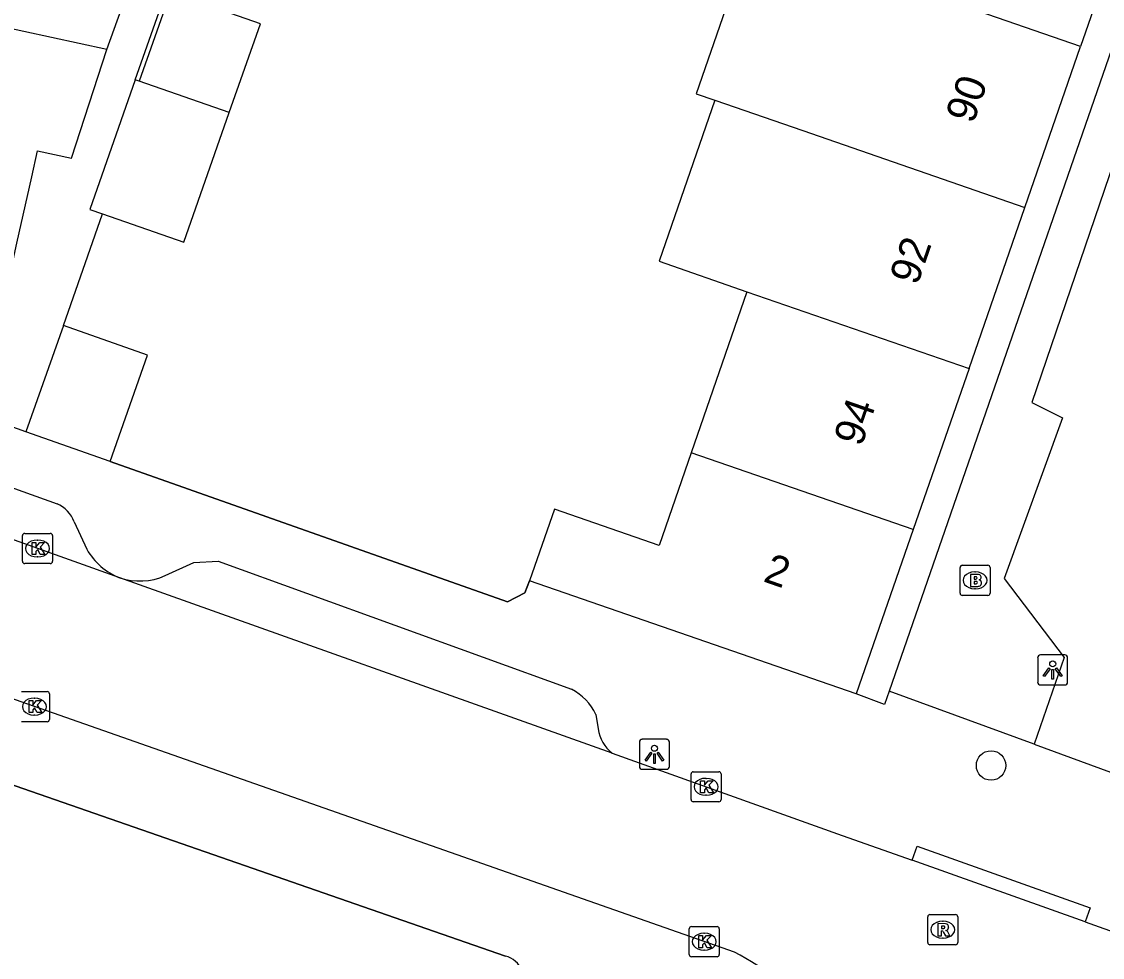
# Model space of a CAD drawing. Extents: x 160356 to 161355, y 381727 to 382845.
# Drawn here: x 160605.96 to 160641.88, y 382098.93 to 382130.04 of the extents above; entities that cross this region are included whole.
import ezdxf

# ---------------------------------------------------------------- set-up
doc = ezdxf.new("R2010")
doc.units = 0
for name, color, linetype in [('IMGEO_Boom', 7, 'Continuous'), ('IMGEO_Brandkraan', 7, 'Continuous'), ('IMGEO_Kolk', 7, 'Continuous'), ('IMGEO_Lichtpunt', 7, 'Continuous'), ('IMGEO_Muur', 7, 'Continuous'), ('IMGEO_Pand', 7, 'Continuous'), ('IMGEO_Pand_nummerreeks', 7, 'Continuous'), ('IMGEO_Rijbaan_lokaal_open', 7, 'Continuous'), ('IMGEO_Rioolput', 7, 'Continuous'), ('IMGEO_Voetpad_open', 7, 'Continuous')]:
    doc.layers.add(name, color=color, linetype=linetype)

msp = doc.modelspace()

# ---------------------------------------------------------------- linework, layer by layer
at = {"layer": 'IMGEO_Boom'}
msp.add_circle((160638.18, 382105.312), 0.489, dxfattribs=at)
at = {"layer": 'IMGEO_Brandkraan'}
for p, q in [((160637.148, 382111.039), (160637.148, 382111.891)), ((160637.223, 382111.965), (160638.075, 382111.965)), ((160637.636, 382111.745), (160637.661, 382111.745)), ((160638.149, 382111.891), (160638.149, 382111.039)), ((160637.659, 382111.185), (160637.634, 382111.185)), ((160638.075, 382110.965), (160637.223, 382110.965))]:
    msp.add_line(p, q, dxfattribs=at)
for points in [[(160637.148, 382111.039), (160637.148, 382111.891)], [(160637.223, 382111.965), (160638.075, 382111.965)], [(160638.149, 382111.891), (160638.149, 382111.039)], [(160637.496, 382111.665), (160637.496, 382111.265), (160637.709, 382111.265)], [(160637.727, 382111.665), (160637.496, 382111.665)], [(160637.675, 382111.584), (160637.621, 382111.584), (160637.621, 382111.508)], [(160637.621, 382111.508), (160637.674, 382111.508)], [(160637.683, 382111.432), (160637.621, 382111.432), (160637.621, 382111.351)], [(160637.621, 382111.351), (160637.683, 382111.351)], [(160638.075, 382110.965), (160637.223, 382110.965)]]:
    msp.add_lwpolyline(points, dxfattribs=at)
for centre, radius, start, end in [((160637.225, 382111.889), 0.0765, 91.552, 178.448), ((160637.225, 382111.889), 0.0765, 91.552, 178.448), ((160638.073, 382111.889), 0.0765, 1.552, 88.448), ((160638.073, 382111.889), 0.0765, 1.552, 88.448), ((160637.676, 382111.546), 0.0379, 267.8285, 90.9355), ((160637.684, 382111.391), 0.0404, 269.8759, 90.5077), ((160637.731, 382111.52), 0.145, 59.4692, 91.5367), ((160637.756, 382111.567), 0.0922, 285.5137, 58.1501), ((160637.761, 382111.375), 0.105, 301.3115, 78.989), ((160637.225, 382111.041), 0.0765, 181.552, 268.448), ((160637.225, 382111.041), 0.0765, 181.552, 268.448), ((160637.715, 382111.516), 0.251, 268.6676, 293.5347), ((160638.073, 382111.041), 0.0765, 271.552, 358.448), ((160638.073, 382111.041), 0.0765, 271.552, 358.448)]:
    msp.add_arc(centre, radius, start, end, dxfattribs=at)
for centre, major_axis, ratio, start_param, end_param in [((160637.635, 382111.465), (-0.387, 0.002), 0.722429, 4.712389, 7.853982), ((160637.66, 382111.465), (-0.39, 0.002), 0.717154, 1.570796, 4.712389)]:
    msp.add_ellipse(centre, major_axis=major_axis, ratio=ratio, start_param=start_param, end_param=end_param, dxfattribs=at)
at = {"layer": 'IMGEO_Kolk'}
for p, q in [((160605.992, 382112.099), (160605.992, 382112.951)), ((160606.067, 382113.025), (160606.919, 382113.025)), ((160606.48, 382112.805), (160606.505, 382112.805)), ((160606.993, 382112.951), (160606.993, 382112.099)), ((160606.503, 382112.245), (160606.478, 382112.245)), ((160606.919, 382112.025), (160606.067, 382112.025)), ((160605.965, 382107.769), (160606.817, 382107.769)), ((160606.378, 382107.549), (160606.403, 382107.549)), ((160606.891, 382107.695), (160606.891, 382106.843)), ((160606.817, 382106.769), (160605.965, 382106.769)), ((160606.401, 382106.989), (160606.376, 382106.989)), ((160628.209, 382104.179), (160628.209, 382105.031)), ((160628.284, 382105.105), (160629.136, 382105.105)), ((160628.697, 382104.885), (160628.722, 382104.885)), ((160629.21, 382105.031), (160629.21, 382104.179)), ((160628.72, 382104.325), (160628.695, 382104.325)), ((160629.136, 382104.105), (160628.284, 382104.105)), ((160628.148, 382099.031), (160628.148, 382099.883)), ((160628.223, 382099.957), (160629.075, 382099.957)), ((160629.149, 382099.883), (160629.149, 382099.031)), ((160628.636, 382099.737), (160628.661, 382099.737)), ((160628.659, 382099.177), (160628.634, 382099.177)), ((160629.075, 382098.957), (160628.223, 382098.957))]:
    msp.add_line(p, q, dxfattribs=at)
for points in [[(160605.992, 382112.099), (160605.992, 382112.951)], [(160606.067, 382113.025), (160606.919, 382113.025)], [(160606.993, 382112.951), (160606.993, 382112.099)], [(160606.313, 382112.725), (160606.436, 382112.725), (160606.436, 382112.574), (160606.566, 382112.725), (160606.73, 382112.725), (160606.584, 382112.574), (160606.737, 382112.325), (160606.585, 382112.325), (160606.5, 382112.489), (160606.436, 382112.422), (160606.436, 382112.325), (160606.313, 382112.325), (160606.313, 382112.725)], [(160606.919, 382112.025), (160606.067, 382112.025)], [(160605.965, 382107.769), (160606.817, 382107.769)], [(160606.211, 382107.469), (160606.334, 382107.469), (160606.334, 382107.318), (160606.464, 382107.469), (160606.628, 382107.469), (160606.482, 382107.318), (160606.635, 382107.069), (160606.483, 382107.069), (160606.398, 382107.233), (160606.334, 382107.166), (160606.334, 382107.069), (160606.211, 382107.069), (160606.211, 382107.469)], [(160606.891, 382107.695), (160606.891, 382106.843)], [(160606.817, 382106.769), (160605.965, 382106.769)], [(160628.209, 382104.179), (160628.209, 382105.031)], [(160628.284, 382105.105), (160629.136, 382105.105)], [(160629.21, 382105.031), (160629.21, 382104.179)], [(160628.53, 382104.805), (160628.653, 382104.805), (160628.653, 382104.654), (160628.783, 382104.805), (160628.947, 382104.805), (160628.801, 382104.654), (160628.954, 382104.405), (160628.802, 382104.405), (160628.717, 382104.569), (160628.653, 382104.502), (160628.653, 382104.405), (160628.53, 382104.405), (160628.53, 382104.805)], [(160629.136, 382104.105), (160628.284, 382104.105)], [(160628.148, 382099.031), (160628.148, 382099.883)], [(160628.223, 382099.957), (160629.075, 382099.957)], [(160629.149, 382099.883), (160629.149, 382099.031)], [(160628.469, 382099.657), (160628.592, 382099.657), (160628.592, 382099.506), (160628.722, 382099.657), (160628.886, 382099.657), (160628.74, 382099.506), (160628.893, 382099.257), (160628.741, 382099.257), (160628.656, 382099.421), (160628.592, 382099.354), (160628.592, 382099.257), (160628.469, 382099.257), (160628.469, 382099.657)], [(160629.075, 382098.957), (160628.223, 382098.957)]]:
    msp.add_lwpolyline(points, dxfattribs=at)
for centre, start, end in [((160606.069, 382112.949), 91.552, 178.448), ((160606.069, 382112.949), 91.552, 178.448), ((160606.917, 382112.949), 1.552, 88.448), ((160606.917, 382112.949), 1.552, 88.448), ((160606.069, 382112.101), 181.552, 268.448), ((160606.069, 382112.101), 181.552, 268.448), ((160606.917, 382112.101), 271.552, 358.448), ((160606.917, 382112.101), 271.552, 358.448), ((160606.815, 382107.693), 1.552, 88.448), ((160606.815, 382107.693), 1.552, 88.448), ((160606.815, 382106.845), 271.552, 358.448), ((160606.815, 382106.845), 271.552, 358.448), ((160628.286, 382105.029), 91.552, 178.448), ((160628.286, 382105.029), 91.552, 178.448), ((160629.134, 382105.029), 1.552, 88.448), ((160629.134, 382105.029), 1.552, 88.448), ((160628.286, 382104.181), 181.552, 268.448), ((160628.286, 382104.181), 181.552, 268.448), ((160629.134, 382104.181), 271.552, 358.448), ((160629.134, 382104.181), 271.552, 358.448), ((160628.225, 382099.881), 91.552, 178.448), ((160628.225, 382099.881), 91.552, 178.448), ((160629.073, 382099.881), 1.552, 88.448), ((160629.073, 382099.881), 1.552, 88.448), ((160628.225, 382099.033), 181.552, 268.448), ((160628.225, 382099.033), 181.552, 268.448), ((160629.073, 382099.033), 271.552, 358.448), ((160629.073, 382099.033), 271.552, 358.448)]:
    msp.add_arc(centre, 0.0765, start, end, dxfattribs=at)
for centre, major_axis, ratio, start_param, end_param in [((160606.479, 382112.525), (-0.387, 0.002), 0.722429, 4.712389, 7.853982), ((160606.504, 382112.525), (-0.39, 0.002), 0.717154, 1.570796, 4.712389), ((160606.377, 382107.269), (-0.387, 0.002), 0.722429, 4.712389, 7.853982), ((160606.402, 382107.269), (-0.39, 0.002), 0.717154, 1.570796, 4.712389), ((160628.696, 382104.605), (-0.387, 0.002), 0.722429, 4.712389, 7.853982), ((160628.721, 382104.605), (-0.39, 0.002), 0.717154, 1.570796, 4.712389), ((160628.635, 382099.457), (-0.387, 0.002), 0.722429, 4.712389, 7.853982), ((160628.66, 382099.457), (-0.39, 0.002), 0.717154, 1.570796, 4.712389)]:
    msp.add_ellipse(centre, major_axis=major_axis, ratio=ratio, start_param=start_param, end_param=end_param, dxfattribs=at)
at = {"layer": 'IMGEO_Lichtpunt'}
for p, q in [((160639.729, 382108.892), (160639.729, 382108.085)), ((160639.729, 382108.892), (160639.729, 382108.085)), ((160640.631, 382108.987), (160639.823, 382108.987)), ((160640.631, 382108.987), (160639.823, 382108.987)), ((160640.725, 382108.085), (160640.725, 382108.892)), ((160640.725, 382108.085), (160640.725, 382108.892)), ((160639.823, 382107.991), (160640.631, 382107.991)), ((160639.823, 382107.991), (160640.631, 382107.991)), ((160626.495, 382106.087), (160626.495, 382105.28)), ((160626.495, 382106.087), (160626.495, 382105.28)), ((160627.397, 382106.182), (160626.589, 382106.182)), ((160627.397, 382106.182), (160626.589, 382106.182)), ((160627.491, 382105.28), (160627.491, 382106.087)), ((160627.491, 382105.28), (160627.491, 382106.087)), ((160626.589, 382105.186), (160627.397, 382105.186)), ((160626.589, 382105.186), (160627.397, 382105.186))]:
    msp.add_line(p, q, dxfattribs=at)
for points in [[(160640.103, 382108.556), (160640.142, 382108.528), (160639.954, 382108.266), (160639.916, 382108.293), (160640.103, 382108.556)], [(160640.205, 382108.508), (160640.252, 382108.508), (160640.252, 382108.186), (160640.205, 382108.186), (160640.205, 382108.508)], [(160640.315, 382108.528), (160640.353, 382108.555), (160640.54, 382108.293), (160640.501, 382108.265), (160640.315, 382108.528)], [(160626.869, 382105.751), (160626.908, 382105.723), (160626.72, 382105.461), (160626.682, 382105.488), (160626.869, 382105.751)], [(160626.971, 382105.703), (160627.018, 382105.703), (160627.018, 382105.381), (160626.971, 382105.381), (160626.971, 382105.703)], [(160627.081, 382105.723), (160627.119, 382105.75), (160627.306, 382105.488), (160627.267, 382105.46), (160627.081, 382105.723)]]:
    msp.add_lwpolyline(points, dxfattribs=at)
for centre in [(160640.228, 382108.69), (160626.994, 382105.885)]:
    msp.add_circle(centre, 0.0994, dxfattribs=at)
for centre, start, end in [((160639.823, 382108.892), 90, 180), ((160639.823, 382108.892), 90, 180), ((160640.631, 382108.892), 0, 90), ((160640.631, 382108.892), 0, 90), ((160639.823, 382108.085), 180, 270), ((160639.823, 382108.085), 180, 270), ((160640.631, 382108.085), 270, 0), ((160640.631, 382108.085), 270, 360), ((160626.589, 382106.087), 90, 180), ((160626.589, 382106.087), 90, 180), ((160627.397, 382106.087), 0, 90), ((160627.397, 382106.087), 0, 90), ((160626.589, 382105.28), 180, 270), ((160626.589, 382105.28), 180, 270), ((160627.397, 382105.28), 270, 0), ((160627.397, 382105.28), 270, 360)]:
    msp.add_arc(centre, 0.0946, start, end, dxfattribs=at)
at = {"layer": 'IMGEO_Muur'}
for points in [[(160608.902, 382115.42), (160622.112, 382110.755), (160622.69, 382111.047), (160622.846, 382111.45)], [(160605.495, 382104.723), (160622.044, 382098.98)]]:
    msp.add_lwpolyline(points, dxfattribs=at)
msp.add_arc((160621.818, 382098.168), 0.843, 332.2333, 74.4505, dxfattribs=at)
at = {"layer": 'IMGEO_Pand'}
for points in [[(160643.011, 382134.564), (160641.156, 382129.211)], [(160633.776, 382131.765), (160630.233, 382132.991), (160628.38, 382127.637), (160629, 382127.423)], [(160641.156, 382129.211), (160633.776, 382131.765)], [(160608.795, 382129.105), (160600.516, 382130.917)], [(160612.866, 382127.015), (160613.9, 382129.961), (160610.912, 382131.011), (160609.873, 382128.052)], [(160604.739, 382117.783), (160605.809, 382122.668), (160606.3, 382124.874), (160606.493, 382125.742), (160607.626, 382125.494), (160608.795, 382129.105)], [(160639.302, 382123.858), (160641.156, 382129.211)], [(160609.74, 382128.098), (160608.23, 382123.796), (160608.658, 382123.646)], [(160609.873, 382128.052), (160609.74, 382128.098)], [(160612.866, 382127.015), (160609.873, 382128.052)], [(160629, 382127.423), (160627.149, 382122.071), (160630.068, 382121.06)], [(160629, 382127.423), (160631.922, 382126.412), (160639.302, 382123.858)], [(160608.658, 382123.646), (160611.351, 382122.7), (160612.866, 382127.015)], [(160637.448, 382118.505), (160639.302, 382123.858)], [(160630.068, 382121.06), (160628.214, 382115.706)], [(160630.068, 382121.06), (160637.448, 382118.505)], [(160607.354, 382119.932), (160606.109, 382116.406)], [(160608.902, 382115.42), (160610.147, 382118.945), (160607.354, 382119.932)], [(160637.448, 382118.505), (160635.594, 382113.151)], [(160608.902, 382115.42), (160606.109, 382116.406)], [(160628.214, 382115.706), (160627.148, 382112.629), (160623.671, 382113.833), (160622.846, 382111.45)], [(160635.594, 382113.151), (160628.214, 382115.706)], [(160635.594, 382113.151), (160633.702, 382107.689)], [(160633.702, 382107.689), (160622.846, 382111.45)]]:
    msp.add_lwpolyline(points, dxfattribs=at)
at = {"layer": 'IMGEO_Rijbaan_lokaal_open'}
for points in [[(160629.655, 382099.104), (160601.548, 382108.97), (160596.436, 382110.567), (160593.301, 382111.46), (160591.369, 382111.972), (160589.005, 382112.481), (160586.145, 382113.154), (160582.43, 382113.733)], [(160609.227, 382111.549), (160604.515, 382113.229)], [(160625.589, 382105.717), (160609.227, 382111.549)], [(160625.589, 382105.717), (160633.236, 382102.991), (160635.554, 382102.164)], [(160641.308, 382100.113), (160635.554, 382102.164)], [(160641.308, 382100.113), (160646.097, 382098.406)]]:
    msp.add_lwpolyline(points, dxfattribs=at)
msp.add_arc((160624.427, 382089.042), 11.339, 45.2236, 62.5465, dxfattribs=at)
at = {"layer": 'IMGEO_Rioolput'}
for p, q in [((160636.075, 382099.43), (160636.075, 382100.282)), ((160636.15, 382100.356), (160637.002, 382100.356)), ((160637.076, 382100.282), (160637.076, 382099.43)), ((160636.563, 382100.136), (160636.588, 382100.136)), ((160636.586, 382099.576), (160636.561, 382099.576)), ((160637.002, 382099.356), (160636.15, 382099.356))]:
    msp.add_line(p, q, dxfattribs=at)
for points in [[(160636.075, 382099.43), (160636.075, 382100.282)], [(160636.15, 382100.356), (160637.002, 382100.356)], [(160637.076, 382100.282), (160637.076, 382099.43)], [(160636.664, 382100.054), (160636.412, 382100.056), (160636.412, 382099.656)], [(160636.59, 382099.975), (160636.536, 382099.975), (160636.536, 382099.894)], [(160636.536, 382099.894), (160636.588, 382099.894)], [(160636.412, 382099.656), (160636.536, 382099.656), (160636.536, 382099.818), (160636.547, 382099.818)], [(160636.594, 382099.789), (160636.665, 382099.656), (160636.805, 382099.656), (160636.74, 382099.782)], [(160637.002, 382099.356), (160636.15, 382099.356)]]:
    msp.add_lwpolyline(points, dxfattribs=at)
for centre, radius, start, end in [((160636.152, 382100.28), 0.0765, 91.552, 178.448), ((160636.152, 382100.28), 0.0765, 91.552, 178.448), ((160637, 382100.28), 0.0765, 1.552, 88.448), ((160637, 382100.28), 0.0765, 1.552, 88.448), ((160636.572, 382100.083), 0.19, 274.7715, 282.9687), ((160636.596, 382099.879), 0.0964, 77.0061, 93.1865), ((160636.61, 382099.936), 0.0378, 276.6634, 79.6772), ((160636.663, 382099.944), 0.109, 350.3612, 89.416), ((160636.661, 382099.944), 0.112, 277.5842, 350.9817), ((160636.546, 382099.765), 0.0533, 26.0293, 88.6989), ((160636.645, 382099.729), 0.108, 29.5134, 73.7905), ((160636.152, 382099.432), 0.0765, 181.552, 268.448), ((160636.152, 382099.432), 0.0765, 181.552, 268.448), ((160637, 382099.432), 0.0765, 271.552, 358.448), ((160637, 382099.432), 0.0765, 271.552, 358.448)]:
    msp.add_arc(centre, radius, start, end, dxfattribs=at)
for centre, major_axis, ratio, start_param, end_param in [((160636.562, 382099.856), (-0.387, 0.002), 0.722429, 4.712389, 7.853982), ((160636.587, 382099.856), (-0.39, 0.002), 0.717154, 1.570796, 4.712389)]:
    msp.add_ellipse(centre, major_axis=major_axis, ratio=ratio, start_param=start_param, end_param=end_param, dxfattribs=at)
at = {"layer": 'IMGEO_Voetpad_open'}
for points in [[(160655.119, 382166.468), (160634.794, 382107.787)], [(160608.795, 382129.105), (160613.766, 382142.911)], [(160609.74, 382128.098), (160611.408, 382132.85), (160612.112, 382134.832)], [(160644.447, 382128.448), (160643.391, 382128.676), (160639.534, 382117.379), (160640.555, 382116.871), (160638.62, 382111.527), (160640.607, 382108.902), (160639.616, 382106.019)], [(160607.354, 382119.932), (160608.658, 382123.646)], [(160606.109, 382116.406), (160604.558, 382116.954), (160604.739, 382117.783)], [(160622.846, 382111.45), (160622.69, 382111.047), (160622.112, 382110.755), (160608.902, 382115.42)], [(160604.147, 382115.078), (160607.142, 382114.009)], [(160607.715, 382113.413), (160608.133, 382112.499)], [(160610.739, 382111.622), (160611.691, 382112.057), (160612.492, 382112.1), (160624.237, 382107.846)], [(160634.794, 382107.787), (160634.64, 382107.343), (160633.702, 382107.689)], [(160639.616, 382106.019), (160634.794, 382107.787)], [(160625.05, 382107.008), (160625.126, 382106.526)], [(160639.616, 382106.019), (160643.02, 382104.771)], [(160622.044, 382098.98), (160605.495, 382104.723)], [(160635.554, 382102.164), (160635.721, 382102.635), (160641.475, 382100.584), (160641.308, 382100.113)]]:
    msp.add_lwpolyline(points, dxfattribs=at)
for centre, radius, start, end in [((160606.711, 382113.021), 1.077, 21.3117, 66.434), ((160610.01, 382113.555), 2.154, 209.3746, 248.685), ((160609.887, 382113.564), 2.121, 251.8526, 293.6757), ((160623.362, 382106.183), 1.879, 26.0314, 62.2335), ((160626.382, 382106.708), 1.269, 188.2358, 231.3302), ((160621.818, 382098.168), 0.843, 332.2333, 74.4505)]:
    msp.add_arc(centre, radius, start, end, dxfattribs=at)

# ---------------------------------------------------------------- texts
at = {"layer": 'IMGEO_Pand_nummerreeks'}
for s, rotation, p in [('90', 70.8978, (160637.589, 382126.609)), ('92', 70.8978, (160635.729, 382121.24)), ('94', 70.8959, (160633.872, 382115.877)), ('2', 340.8916, (160630.575, 382111.44))]:
    msp.add_text(s, height=1, rotation=rotation, dxfattribs=at).set_placement(p)

doc.saveas('drawing.dxf')
